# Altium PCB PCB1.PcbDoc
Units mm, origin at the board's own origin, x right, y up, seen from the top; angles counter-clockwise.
Board outline 39.96 x 24.01 mm, 2 copper layers (Top Layer, Bottom Layer); 23 components, 17 nets, 101 pads, 21 vias.
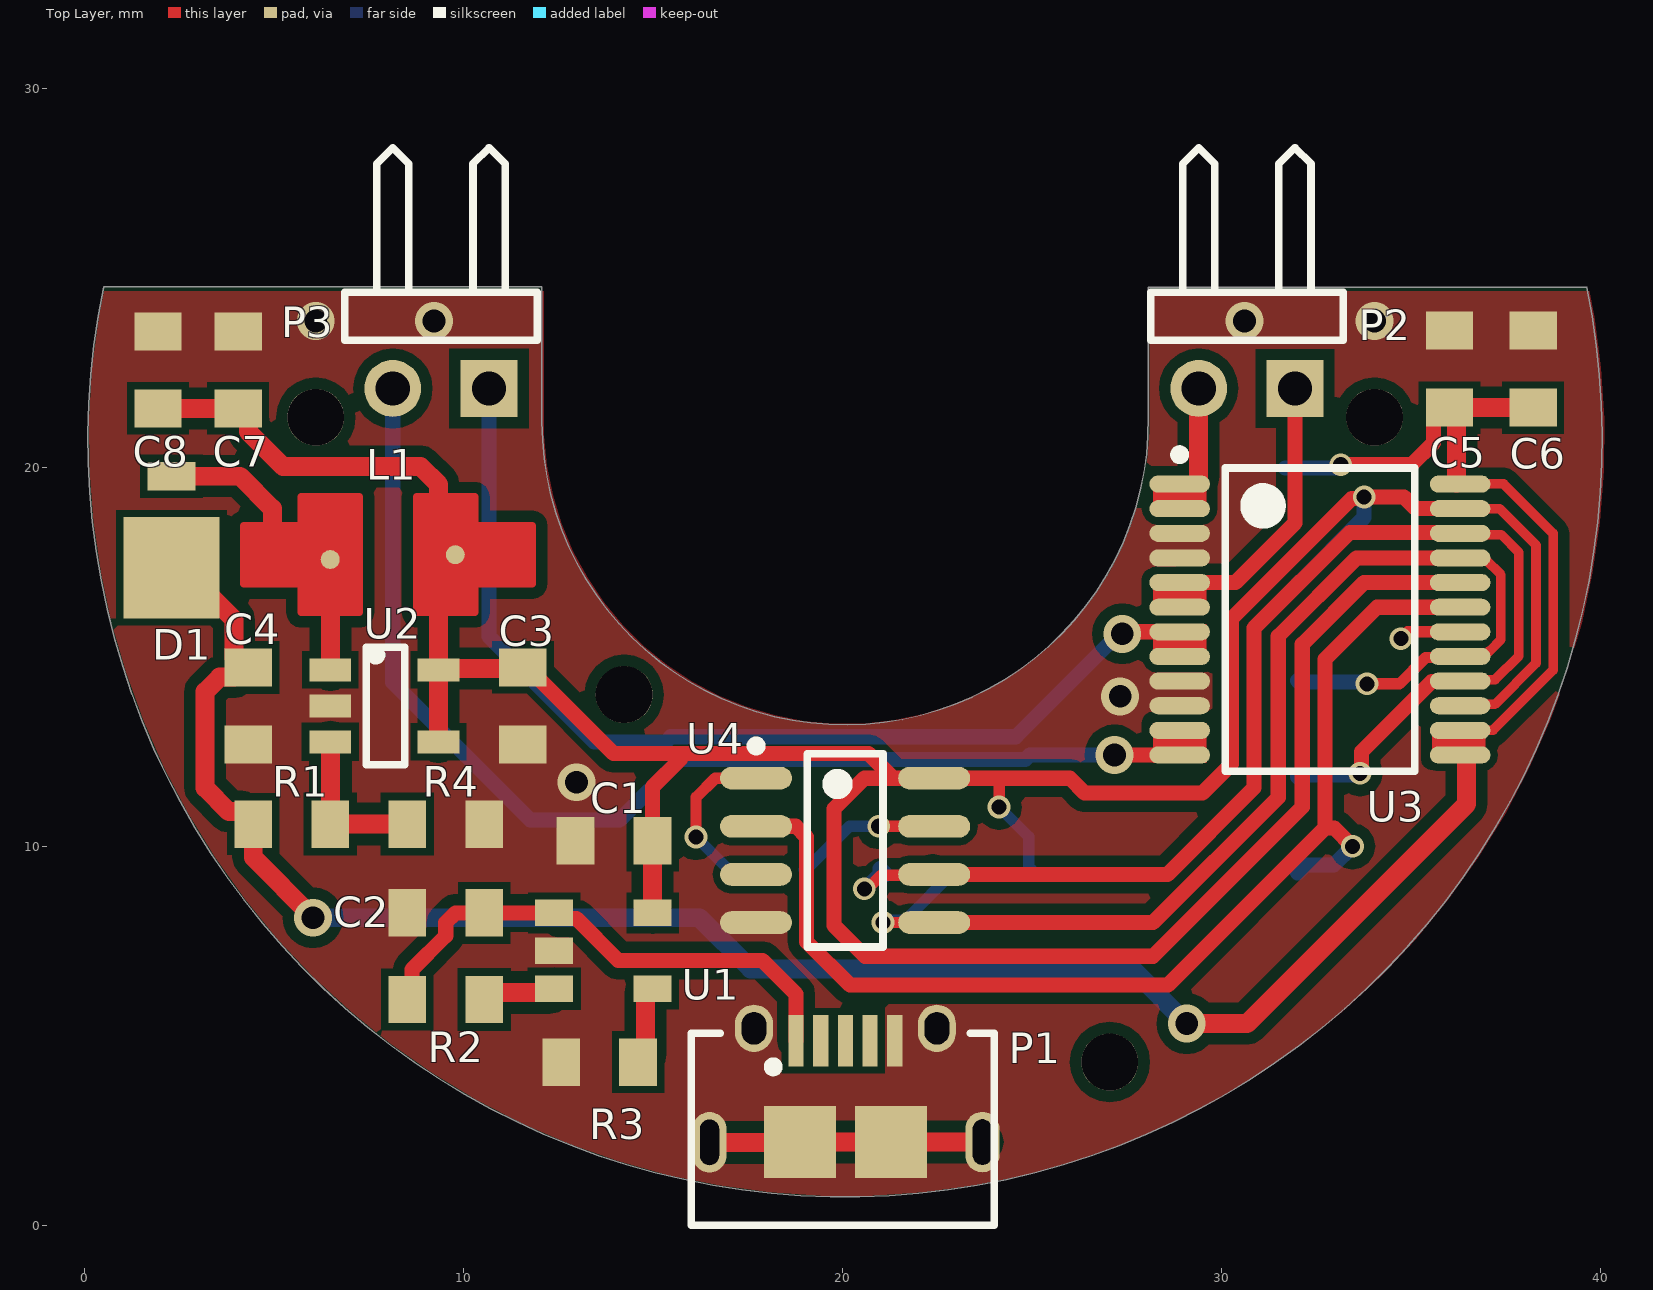
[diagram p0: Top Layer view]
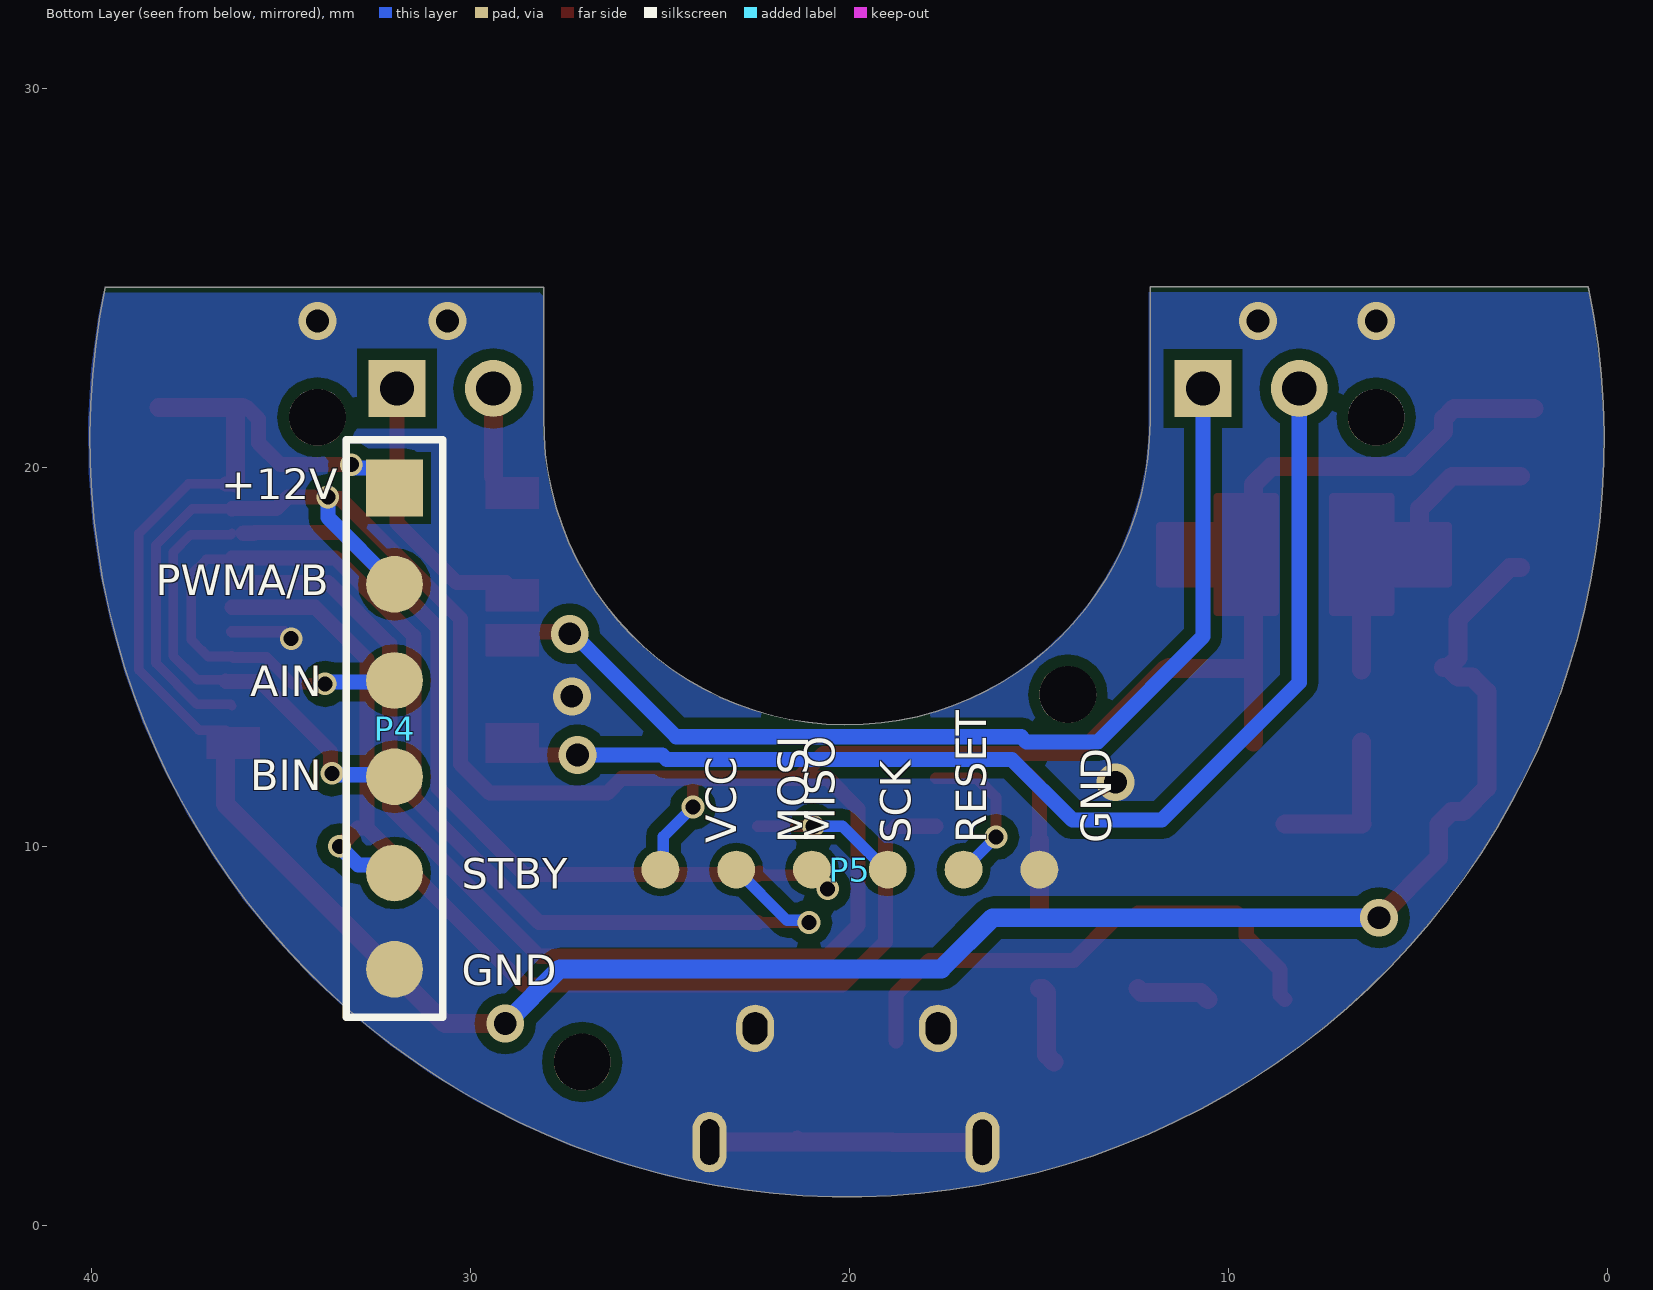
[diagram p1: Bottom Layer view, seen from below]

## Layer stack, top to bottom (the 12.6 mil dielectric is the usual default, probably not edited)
Top Solder: solder mask 0.0102, Solder Resist, Dk 3.5
Top Layer: signal copper 0.0356
Dielectric 1: dielectric 0.32, FR-4, Dk 4.8
Bottom Layer: signal copper 0.0356
Bottom Solder: solder mask 0.0102, Solder Resist, Dk 3.5

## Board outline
0.494,24.776 ccw(c20.066,20.745) 39.639,24.768 39.634,24.773 28.065,24.773 28.065,21.334 cw(c20.066,21.216) 12.066,21.216 12.066,24.775

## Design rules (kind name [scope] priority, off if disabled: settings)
Clearance [All] p1: gap=0.3 ignorepadtopadclearanceinfootprint=FALSE except(0.15: Arc-SMDPad Track-SMDPad SMDPad-SMDPad; 0.2: Arc-Arc Arc-Track Track-Track SMDPad-Fill SMDPad-Poly SMDPad-Region)
PlaneConnect [All] p1: planeconnectstyle=Direct reliefexpansion=0.508 reliefentries=4 reliefconductorwidth=0.254 reliefairgap=0.254
PolygonConnect [All] p1: connectstyle=Direct reliefconductorwidth=0.254 reliefentries=4 polygonreliefangle="90 Angle" airgapwidth=0.254
RoutingVias [All] p1: holewidth=0.3 width=0.4 viastyle="Through Hole" minholewidth=0.3 minwidth=0.3 maxholewidth=0.711 maxwidth=1.27
SolderMaskExpansion [All] p1: expansion=0.102
Width [All] p1: maxlimit=0.5 minlimit=0.254 preferedwidth=0.4 minimp=50.000000 maximp=50.000000 favimp=50.000000
29 further rules are at their usual default settings.

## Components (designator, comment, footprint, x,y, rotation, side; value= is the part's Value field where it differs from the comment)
C1 "0.1uF" CAP0805 13.97,10.16 r0 top
C2 "10uF" CAP0805 9.525,8.255 r0 top
C3 "2.2uF" CAP0805 11.559,13.718 r90 top
C4 "10uF" CAP0805 4.318,13.716 r90 top
C5 "10uF" CAP0805 36.016,22.606 r270 top
C6 "0.1uF" CAP0805 38.227,22.606 r270 top
C7 "10uF" CAP0805 4.048,22.587 r270 top
C8 "0.1uF" CAP0805 1.933,22.587 r270 top
D1 "MBRM140T3G" MBRM140T3G 2.286,17.367 r90 top
L1 "10uH" LQH43CN100K03L 9.779,17.709 r180 top value=10mH
P1 "Micro USB" "MICRO USB" 20.066,3.556 r0 top locked
P2 "Header 2H" HDR1X2H 31.938,22.098 r180 top locked
P3 "Header 2H" HDR1X2H 10.668,22.098 r180 top locked
P4 "Header 6" HDR1X6 32.004,19.469 r270 bottom
P5 "ICSP Conn." "ICSP Conn." 19.987,9.398 r180 bottom
R1 "43.2k" RES0805 5.461,10.597 r180 top
R2 "0" RES0805 9.525,5.969 r0 top
R3 "374Ω" RES0805 13.589,4.318 r0 top
R4 "5k" RES0805 9.525,10.597 r180 top
U1 "FPF2124" SOT23-5 15.486,5.855 r0 top
U2 "MIC2288YD5-TR" MIC2288YD5-TR 7.964,13.662 r0 top
U3 "TB6612FNG" TOSH-SSOP-24_M 32.596,15.998 r0 top
U4 "ATtiny13A-SSH" 8S1_L 20.066,9.906 r0 top

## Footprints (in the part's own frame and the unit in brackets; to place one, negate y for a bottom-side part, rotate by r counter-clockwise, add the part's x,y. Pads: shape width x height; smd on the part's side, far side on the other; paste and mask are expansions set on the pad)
8S1_L [mm] "SOIC, 8-Leads, Body 4.9x3.9mm, Pitch 1.27mm, IPC High Density"
  oval 1.9x0.6 smd: 1(-2.35,1.905) 2(-2.35,0.635) 3(-2.35,-0.635) 4(-2.35,-1.905) 5(2.35,-1.905) 6(2.35,-0.635) 7(2.35,0.635) 8(2.35,1.905)
  silkscreen extent -2.47,-2.55 1,2.88, body extent -1.99,-2.52 1.99,2.52, height 1.75
CAP0805 [mm]
  rect 1x1.25 smd: 1(-1.016,0) 2(1.016,0)
  body extent -1.1,-0.72 1.11,0.72, height 0.94
HDR1X2H [mm] "Connector; Header; 2 Position; Right Angle"
  rect 1.5x1.5 hole 0.9: 1(0,0)
  round 1.5 hole 0.9: 2(2.54,0)
  silkscreen extent -1.27,-6.35 3.81,-1.27
HDR1X6 [mm] "Connector; Header; 6 Position"
  rect 1.5x1.5 smd: 1(0,0)
  round 1.5 smd: 2(2.54,0) 3(5.08,0) 4(7.62,0) 5(10.16,0) 6(12.7,0)
  silkscreen extent -1.27,-1.27 13.97,1.27
"ICSP Conn." [mm]
  round 1 smd: 1(-5,0) 2(-3,0) 3(-1,0) 4(1,0) 5(3,0) 6(5,0)
LQH43CN100K03L [mm]
  round 0.5 smd: 1(0,0) 2(3.302,0.127)
  Top Layer region: -2.032,-0.762 -0.508,-0.762 -0.508,-1.524 1.016,-1.524 1.016,1.524 -0.508,1.524 -0.508,0.762 -2.032,0.762
  Top Layer region: 2.54,-1.524 2.54,1.524 4.064,1.524 4.064,0.762 5.588,0.762 5.588,-0.762 4.064,-0.762 4.064,-1.524
  Top Layer lines w0.2: 0.889,-0.063 0.889,-0.254 ; 1.016,1.207 1.016,0.953 ; 1.016,1.207 1.016,1.524 0.825,1.524 0.7,1.524 0.446,1.524 -0.508,1.524 -0.508,0.762 -2.032,0.762 -2.032,-0.762 -0.508,-0.762 -0.508,-1.524 0,-1.524 0.444,-1.524 0.826,-1.524 0.83,-1.524 1.016,-1.524 1.016,-1.016 1.016,-0.707 1.016,-0.167 1.016,-0.063 1.016,0 1.016,0.191 1.016,0.445 1.016,0.953 ; 1.016,1.207 1.016,0.953 ; 5.588,0.762 4.064,0.762 4.064,1.524 3.551,1.524 3.321,1.524 3.297,1.524 2.54,1.524 2.54,-1.524 4.064,-1.524 4.064,-0.762 4.191,-0.762 4.624,-0.762 4.826,-0.762 4.882,-0.762 5.588,-0.762 5.588,0.762
MBRM140T3G [mm]
  rect 2.67x2.54 smd: 1(0,0)
  rect 0.76x1.27 smd: 2(2.413,0)
MIC2288YD5-TR [mm]
  rect 1.1x0.6 smd: 1(-1.482,1.006) 2(-1.482,0.056) 3(-1.482,-0.894) 4(1.369,-0.894) 5(1.369,1.006)
  silkscreen extent -0.54,-1.49 0.48,1.61, body extent -1.43,-1.37 1.37,1.53, height 1.45
"MICRO USB" [mm]
  rect 0.4x1.35 smd: 1(-1.292,1.326) 2(-0.642,1.326) 3(0.008,1.326) 4(0.658,1.326) 5(1.308,1.326)
  oval 0.9x1.6 hole 0.5 slot 1.2 at 90 deg: 6(-3.578,-1.355) 6(3.622,-1.349)
  oval 1x1.25 hole 0.85 slot 0.65 at 0 deg: 6(-2.405,1.652) 6(2.421,1.652)
  rect 1.9x1.9 smd: 6(-1.192,-1.349) 6(1.208,-1.349)
  silkscreen extent -4.06,-3.55 3.94,1.53, body extent -3.92,-4.16 3.94,1.5, height 2.83
RES0805 [mm]
  rect 1x1.25 smd: 1(-1.016,0) 2(1.016,0)
  body extent -1.1,-0.72 1.11,0.72, height 0.94
SOT23-5 [mm]
  rect 1x0.7 smd: 1(-3.1,2.4) 2(-3.1,1.4) 3(-3.1,0.4) 4(-0.5,0.4) 5(-0.5,2.4)
TOSH-SSOP-24_M [mm] "SOP, 24-Leads, Body 8x5.8mm, Pitch 0.65mm, IPC Low Density"
  oval 1.6x0.45 smd: 1(-3.7,3.575) 2(-3.7,2.925) 3(-3.7,2.275) 4(-3.7,1.625) 5(-3.7,0.975) 6(-3.7,0.325) 7(-3.7,-0.325) 8(-3.7,-0.975) 9(-3.7,-1.625) 10(-3.7,-2.275) 11(-3.7,-2.925) 12(-3.7,-3.575) 13(3.7,-3.575) 14(3.7,-2.925) 15(3.7,-2.275) 16(3.7,-1.625) 17(3.7,-0.975) 18(3.7,-0.325) 19(3.7,0.325) 20(3.7,0.975) 21(3.7,1.625) 22(3.7,2.275) 23(3.7,2.925) 24(3.7,3.575)
  silkscreen extent -3.82,-4 2.5,4.47, body extent -3.8,-4 3.8,4, height 1.6

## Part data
C1 C2: library part Cap, "0603"
C3 C4 C5 C6 C7 C8: library part CAP
D1: library part "Diode 10TQ035", "Schottky Rectifier"
L1: library part Inductor, "Inductor"
P2 P3: "Header, 2-Pin, Right Angle"
P4: "Header, 6-Pin"
R1 R4: library part RES
R2 R3: library part Resistor, "0603"
U3: library part CMP-1773-00001-1, "Driver IC for Dual DC Motor, 15 V, -20 to 85 degC, 24-Pin SSOP, RoHS, Tape and Reel", Case\Package=TO-236-3, Forward Current="70 mA", Forward Voltage="1 V", Max Operating Temperature="125 degC", Max Power Dissipation="200 mW", Max Surge Current="100 mA", Min Operating Temperature="-55 degC", Package Quantity=3000, Peak Reverse Current="0.1 uA"
U4: library part CMP-0093-00145-2, "8-bit AVR Microcontroller, 1.8-5.5V, 20MHz, 1KB Flash, 64 Bytes EEPROM, 64 Bytes SRAM, 8-pin SOIC, Industrial Grade (-40°C to 85°C), Pb-Free"

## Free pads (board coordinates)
  round 1.5 hole 1.5: 5(6.096,21.336) 5(14.235,14.017) 5(27.051,4.318) 5(34.039,21.336)

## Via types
v1: diameter 1, hole 0.6, Top Layer to Bottom Layer, tented both sides, 9 vias
v2: diameter 0.6, hole 0.4, Top Layer to Bottom Layer, tented both sides, 6 vias
v3: diameter 0.6, hole 0.4, Top Layer to Bottom Layer, 5 vias
v4: diameter 1, hole 0.6, Top Layer to Bottom Layer, 1 vias

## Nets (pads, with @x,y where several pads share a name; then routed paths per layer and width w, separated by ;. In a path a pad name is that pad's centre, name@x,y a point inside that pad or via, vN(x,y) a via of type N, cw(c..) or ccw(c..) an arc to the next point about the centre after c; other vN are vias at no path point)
+5V: C1.2 C3.2 C7.2 C8.2 L1.1 P4.2 P5.1 U1.5 U2.4 U2.5 U3.15 U3.20 U3.23 U4.8 | length 95.3
  Top Layer w0.254: U3.15 36.334,13.761 37.212,13.761 38.3,14.848 38.3,17.961 37.338,18.923 U3.23
  Top Layer w0.3: v3(24.13,11.049) 24.13,11.811
  Top Layer w0.4: C3.2 11.684,14.734 13.957,12.461 20.686,12.461 21.336,11.811 ; C1.2 14.986,11.574 15.715,12.303 ; U3.20 33.76,16.973 32.131,15.344 32.131,11.049 28.194,7.112 20.588,7.112 19.774,7.926 19.774,11.004 20.581,11.811 21.336,11.811 ; U3.23 36.287,18.933 35.118,18.933 34.818,19.233 v2(33.765,19.233) 33.727,19.195 33.436,19.195 30.261,16.019 30.261,12.183 29.501,11.423 26.381,11.423 25.993,11.811 24.13,11.811 U4.8 21.336,11.811
  Top Layer w0.5: C8.2 C7.2 4.318,21.301 4.318,20.955 5.237,20.036 8.863,20.036 9.335,19.563 9.335,19.233 9.588,18.98 L1.1@9.588,17.772 ; 9.144,17.772 L1.1@9.588,17.772 ; U2.4 U2.5 ; 9.333,16.185 U2.5 ; 9.779,17.963 L1.1@9.588,17.772 ; L1.1@9.842,17.518 10.033,17.709 ; C3.2 11.526,14.701 9.366,14.701 U2.5 ; U1.5 C1.2
  Bottom Layer w0.3: v3(24.13,11.049) 24.908,10.271 24.908,9.477 P5.1
  Bottom Layer w0.4: P4.2 33.765,18.69 v2(33.765,19.233)
+12V: C4.2 C5.2 C6.2 D1.1 P4.1 R1.2 U3.13 U3.14 U3.24 | length 66.8
  Top Layer w0.254: U3.14@36.466,13.077 37.171,13.077 38.754,14.66 38.754,18.269 37.446,19.577 U3.24@36.466,19.577
  Top Layer w0.4: v2(33.147,20.086) 35.021,20.086 35.591,20.656 35.591,21.29 35.891,21.59 C5.2 ; U3.24 36.462,19.573 U3.24@36.466,19.577
  Top Layer w0.5: D1.1 2.572,17.367 3.943,15.996 3.943,14.982 C4.2@4.193,14.732 ; C4.2 C4.2@4.193,14.732 ; v1(6.022,8.128) 6.022,8.143 4.445,9.72 R1.2 4.112,10.93 3.802,10.93 3.175,11.557 3.175,14.097 3.556,14.478 3.939,14.478 C4.2@4.193,14.732 ; v1(29.083,5.334) 30.673,5.334 36.466,11.127 U3.13@36.466,12.423 ; C5.2 C5.2@36.066,21.59 ; U3.24@36.203,19.602 36.203,21.452 C5.2@36.066,21.59 ; C6.2 C5.2@36.066,21.59
  Bottom Layer w0.4: P4.1@31.682,19.998 33.059,19.998 v2(33.147,20.086)
  Bottom Layer w0.5: v1(6.022,8.128) 16.223,8.128 17.572,6.779 27.638,6.779 v1(29.083,5.334)
AIN: P4.3 P5.2 U3.17 U3.21 U4.5 | length 33
  Top Layer w0.254: U3.17 36.924,15.023 37.072,15.171 37.079,15.171 37.373,15.465 37.373,17.181 36.969,17.585 U3.21@36.334,17.585
  Top Layer w0.3: v3(21.066,8.001) U4.5 ; v2(33.839,14.3) 34.694,14.3 35.388,14.994 36.268,14.994 U3.17
  Top Layer w0.4: U4.5 28.194,8.001 31.496,11.303 31.496,15.557 33.562,17.623 U3.21
  Bottom Layer w0.3: v3(21.066,8.001) 21.123,8.058 21.647,8.058 P5.2
  Bottom Layer w0.4: P4.3 32.048,14.345 33.795,14.345 v2(33.839,14.3)
BIN: P4.4 P5.3 U3.16 U3.22 U4.6 | length 34.9
  Top Layer w0.254: U3.16 36.334,14.411 37.22,14.411 37.846,15.036 37.846,17.773 37.383,18.236 36.334,18.236 U3.22
  Top Layer w0.3: v3(20.574,8.89) 20.655,8.89 21.016,9.251 22.319,9.251 U4.6@22.378,9.309
  Top Layer w0.4: U4.6@22.378,9.309 U4.6 28.575,9.271 30.861,11.557 30.861,15.771 33.384,18.294 35.704,18.294 35.721,18.277 U3.22@35.995,18.277 ; v2(33.655,11.938) 33.693,11.976 33.693,12.508 35.549,14.363 36.452,14.363 U3.16@36.466,14.377
  Bottom Layer w0.3: v3(20.574,8.89) 20.574,8.937 20.987,9.35 P5.3
  Bottom Layer w0.4: P5.3 20.987,9.43 P5.3@21.146,9.271 ; P4.4 32.054,11.9 33.617,11.9 v2(33.655,11.938)
GND: C1.1 C2.1 C3.1 C4.1 C5.1 C6.1 C7.1 C8.1 P1.5 P1.6 P4.6 P5.6 R3.1 R4.1 U1.2 U2.2 U3.3 U3.4 U3.9 U3.10 U3.18 U4.4 | length 9
  Top Layer w0.3: v2(34.733,15.494) 34.912,15.673 U3.18
  Top Layer w0.4: P1.6@21.274,2.207 P1.6@21.374,2.307
  Top Layer w0.5: P1.6@16.488,2.201 18.868,2.201 18.874,2.207 21.274,2.207 P1.6@23.688,2.207
  other v1: 12.977,11.704 6.096,23.876 9.213,23.876 30.607,23.876 34.039,23.876
  other v4: 27.325,13.97
NetD1_2: D1.2 L1.2 U2.1 | length 7.4
  Top Layer w0.5: D1.2 4.1,19.78 4.953,18.927 4.953,18.471 4.953,18.073 5.246,17.78 6.279,17.78 L1.2 6.731,17.582 ; U2.1 6.482,16.185
NetP2_1: P2.1 U3.5 U3.6 | length 7.1
  Top Layer w0.4: U3.5@29.066,16.977 30.37,16.977 31.938,18.545 P2.1
NetP2_2: P2.2 U3.1 U3.2 | length 2.3
  Top Layer w0.5: U3.1@29.398,19.768 P2.2
NetP3_1: P3.1 U3.7 U3.8 | length 27.3
  Top Layer w0.4: v1(27.381,15.621) 27.437,15.677 U3.7@29.066,15.677
  Bottom Layer w0.4: P3.1 10.668,15.546 13.447,12.767 15.33,12.767 15.466,12.903 24.57,12.903 27.288,15.621 v1(27.381,15.621)
NetP3_2: P3.2 U3.11 U3.12 | length 30.9
  Top Layer w0.4: v1(27.178,12.423) U3.12 29.024,12.423 29.047,12.446 U3.12@29.066,12.427
  Bottom Layer w0.4: P3.2 8.128,14.334 11.758,10.704 14.116,10.704 15.715,12.303 24.818,12.303 24.938,12.423 v1(27.178,12.423)
NetR1_1: R1.1 R4.2 U2.3 | length 4.2
  Top Layer w0.5: U2.3 6.479,12.766 6.479,10.599 R1.1 R4.2
NetR2_2: R2.2 U1.3 | length 2
  Top Layer w0.5: R2.2 10.727,6.155 12.286,6.155 U1.3
NetR3_2: R3.2 U1.4 | length 2.1
  Top Layer w0.5: R3.2 14.795,4.508 14.795,6.155 14.896,6.255 U1.4
RES: P5.5 U4.1 | length 4.1
  Top Layer w0.3: v3(16.129,10.256) 16.129,11.303 16.637,11.811 U4.1
  Bottom Layer w0.3: v3(16.129,10.256) P5.5
SCK: P5.4 U4.7 | length 3.9
  Top Layer w0.3: v3(20.955,10.541) U4.7
  Bottom Layer w0.3: P5.4 19.038,9.398 20.181,10.541 v3(20.955,10.541)
STBY: P4.5 U3.19 U4.2 | length 31.3
  Top Layer w0.4: U4.2 18.765,10.541 19.05,10.256 19.05,7.493 20.193,6.35 28.589,6.35 32.731,10.492 ; v2(33.456,10.012) 32.975,10.492 32.731,10.492 ; U3.19 34.103,16.323 32.731,14.951 32.731,10.492
  Bottom Layer w0.4: P4.5 32.214,9.52 32.964,9.52 v2(33.456,10.012)
VIN: C2.2 P1.1 R2.1 U1.1 | length 13.9
  Top Layer w0.4: R2.1 8.636,6.096 8.636,6.762 9.525,7.651 9.525,8.001 9.779,8.255 C2.2 U1.1 12.536,8.105 12.977,8.105 14.08,7.002 17.89,7.002 18.774,6.118 P1.1
pads on no net: P1.2 P1.3 P1.4 U4.3

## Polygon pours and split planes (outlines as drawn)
GND on Bottom Layer "Bottom Layer-GND" (solid, pour order 9): 0.496,24.638 ccw(c20.096,20.744) 39.698,24.625 28.095,24.63 28.095,21.333 cw(c20.096,21.216) 12.096,21.216 12.096,24.637
no net on Bottom Layer "Bottom Layer-No Net" (solid, pour order 2): 64.135,-20.447
GND on Top Layer "Top Layer-GND" (solid, pour order 8): 0.508,24.663 ccw(c20.107,20.769) 39.708,24.66 28.107,24.665 28.107,21.358 cw(c20.107,21.24) 12.107,21.24 12.107,24.662

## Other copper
Top Layer:
  region net +12V: 35.56,13.16 36.957,13.16 36.957,12.324 35.56,12.324
  region net NetP3_2: 28.194,13.264 29.591,13.264 29.591,12.22 28.194,12.22
  region net NetP2_2: 28.194,19.755 29.591,19.755 29.591,18.923 28.194,18.923
  region net NetP3_1: 28.194,15.875 29.591,15.875 29.591,15.023 28.194,15.023
  region: 29.972,19.304
  region net NetP2_1: 28.194,17.055 29.591,17.055 29.591,16.219 28.194,16.219
Bottom Layer:
  region: 7.62,30.607

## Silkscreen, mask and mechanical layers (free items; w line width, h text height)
Bottom Overlay:
  text "+12V" at 36.576,19.177 h0.8
  text "PWMA/B" at 38.3,16.637 h0.8
  text "AIN" at 35.814,13.97 h0.8
  text "BIN" at 35.814,11.498 h0.8
  text "STBY" at 30.226,8.89 h0.8
  text "GND" at 30.226,6.35 h0.8
Mechanical 1:
  lines w0.2: 0.494,24.776 ccw(c20.066,20.745) 39.639,24.768 ; 0.495,24.775 12.066,24.775 12.066,21.216 ccw(c20.066,21.216) 28.065,21.334 28.065,24.773 39.634,24.773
